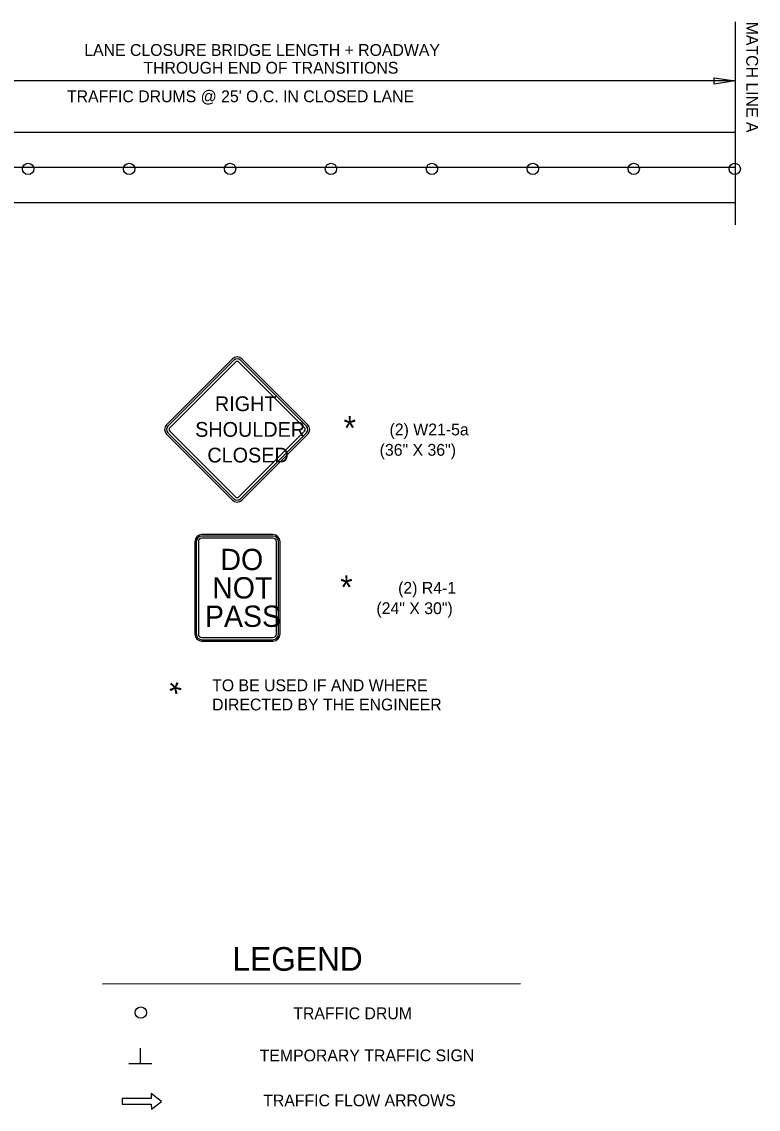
# Model space of a CAD drawing. Extents: x 1925873 to 1930787, y 596452 to 599617.
# Drawn here: x 1926416 to 1926790, y 596949 to 597501 of the extents above; entities that cross this region are included whole.
import ezdxf

# ---------------------------------------------------------------- set-up
doc = ezdxf.new("R2010")
doc.units = 0
for name, color, linetype in [('Default', 7, 'Continuous'), ('P_TC_Signs_Permanent', 7, 'Continuous'), ('P_TC_Signs_Temporary', 7, 'Continuous'), ('R_Border', 7, 'Continuous'), ('R_Border Prem', 7, 'Continuous'), ('R_MOT', 7, 'Continuous')]:
    doc.layers.add(name, color=color, linetype=linetype)

msp = doc.modelspace()

# ---------------------------------------------------------------- linework, layer by layer
at = {"layer": 'Default'}
for p, q in [((1926778.09, 597500.68), (1926778.09, 597397.67)), ((1926778.09, 597470.66), (1926333.71, 597470.66)), ((1926767.55, 597469.08), (1926767.55, 597472.24)), ((1926767.55, 597472.24), (1926778.09, 597470.66)), ((1926778.09, 597470.66), (1926767.55, 597469.08)), ((1925910.15, 597444.67), (1926778.09, 597444.67)), ((1925910.15, 597426.89), (1926778.09, 597426.89)), ((1925910.15, 597409.1), (1926778.09, 597409.1))]:
    msp.add_line(p, q, dxfattribs=at)
for centre in [(1926419.73, 597426.05), (1926470.9, 597426.05), (1926522.06, 597426.05), (1926573.22, 597426.05), (1926624.39, 597426.05), (1926675.55, 597426.05), (1926726.71, 597426.05), (1926777.88, 597426.05), (1926476.84, 596998.21)]:
    msp.add_circle(centre, 2.88, dxfattribs=at)
at = {"layer": 'P_TC_Signs_Permanent'}
for p, q in [((1926504.19, 597237.01), (1926504.19, 597190.21)), ((1926504.91, 597237.01), (1926504.91, 597190.21)), ((1926505.99, 597237.01), (1926505.99, 597190.21)), ((1926543.79, 597240.61), (1926507.79, 597240.61)), ((1926543.79, 597239.89), (1926507.79, 597239.89)), ((1926543.79, 597238.81), (1926507.79, 597238.81)), ((1926545.59, 597190.21), (1926545.59, 597237.01)), ((1926546.67, 597190.21), (1926546.67, 597237.01)), ((1926547.39, 597190.21), (1926547.39, 597237.01)), ((1926507.79, 597188.41), (1926543.79, 597188.41)), ((1926507.79, 597187.33), (1926543.79, 597187.33)), ((1926507.79, 597186.61), (1926543.79, 597186.61))]:
    msp.add_line(p, q, dxfattribs=at)
for centre, radius, start, end in [((1926507.79, 597237.01), 3.6, 90, 180), ((1926507.79, 597237.01), 2.88, 90, 180), ((1926507.79, 597237.01), 1.8, 90, 180), ((1926543.79, 597237.01), 3.6, 360, 90), ((1926543.79, 597237.01), 2.88, 360, 90), ((1926543.79, 597237.01), 1.8, 360, 90), ((1926507.79, 597190.21), 3.6, 180, 270), ((1926507.79, 597190.21), 2.88, 180, 270), ((1926507.79, 597190.21), 1.8, 180, 270), ((1926543.79, 597190.21), 3.6, 270, 360), ((1926543.79, 597190.21), 2.88, 270, 360), ((1926543.79, 597190.21), 1.8, 270, 360)]:
    msp.add_arc(centre, radius, start, end, dxfattribs=at)
at = {"layer": 'P_TC_Signs_Temporary'}
for p, q in [((1926489.87, 597296.31), (1926523.28, 597329.72)), ((1926490.53, 597295.64), (1926523.94, 597329.06)), ((1926491.46, 597294.72), (1926524.87, 597328.13)), ((1926526.46, 597328.13), (1926559.87, 597294.72)), ((1926527.39, 597329.06), (1926560.8, 597295.64)), ((1926528.05, 597329.72), (1926561.46, 597296.31)), ((1926523.28, 597258.12), (1926489.87, 597291.53)), ((1926523.94, 597258.79), (1926490.53, 597292.2)), ((1926524.87, 597259.71), (1926491.46, 597293.13)), ((1926559.87, 597293.13), (1926526.46, 597259.71)), ((1926560.8, 597292.2), (1926527.39, 597258.79)), ((1926561.46, 597291.53), (1926528.05, 597258.12))]:
    msp.add_line(p, q, dxfattribs=at)
for centre, radius, start, end in [((1926525.66, 597327.33), 3.38, 45, 135), ((1926525.66, 597327.33), 2.44, 45, 135), ((1926525.66, 597327.33), 1.13, 45, 135), ((1926492.25, 597293.92), 3.37, 135, 225), ((1926492.25, 597293.92), 2.44, 135, 225), ((1926492.25, 597293.92), 1.12, 135, 225), ((1926559.07, 597293.92), 1.12, 315, 45), ((1926559.07, 597293.92), 2.44, 315, 45), ((1926559.07, 597293.92), 3.37, 315, 45), ((1926525.66, 597260.51), 2.44, 225, 315), ((1926525.66, 597260.51), 1.13, 225, 315), ((1926525.66, 597260.51), 3.38, 225, 315)]:
    msp.add_arc(centre, radius, start, end, dxfattribs=at)
at = {"layer": 'R_Border'}
for p, q in [((1926457.41, 597012.85), (1926669.31, 597012.99)), ((1926476.59, 596972.34), (1926476.58, 596980.2)), ((1926482.32, 596972.17), (1926470.8, 596972.16))]:
    msp.add_line(p, q, dxfattribs=at)
at = {"layer": 'R_MOT'}
msp.add_lwpolyline([(1926482.15, 596949.21), (1926487.34, 596953.21), (1926482.14, 596957.21), (1926482.14, 596954.71), (1926467.43, 596954.7), (1926467.43, 596951.7), (1926482.14, 596951.71)], close=True, dxfattribs=at)

# ---------------------------------------------------------------- texts
at = {"layer": 'Default'}
for s, height, rotation, p in [('MATCH LINE A', 6, 270, (1926783.72, 597500.68)), ('LANE CLOSURE BRIDGE LENGTH + ROADWAY ', 5.9996, 360, (1926448.14, 597483.35)), ('THROUGH END OF TRANSITIONS', 5.9996, 360, (1926478.13, 597474.35)), ("TRAFFIC DRUMS @ 25' O.C. IN CLOSED LANE", 5.9996, 360, (1926439.4, 597459.87))]:
    msp.add_text(s, height=height, rotation=rotation, dxfattribs=at).set_placement(p)
at = {"layer": 'P_TC_Signs_Permanent'}
for s, rotation, p in [('DO', 360, (1926517.18, 597222.61)), ('NOT', 359.9596, (1926513, 597208.22)), ('PASS', 360, (1926509.34, 597193.81))]:
    msp.add_text(s, height=10.8, rotation=rotation, dxfattribs=at).set_placement(p)
at = {"layer": 'P_TC_Signs_Temporary'}
for s, p in [('RIGHT', (1926514.39, 597303.22)), ('SHOULDER', (1926504.37, 597290.2)), ('CLOSED', (1926510.55, 597277.18))]:
    msp.add_text(s, height=7.5, rotation=360, dxfattribs=at).set_placement(p)
at = {"layer": 'R_Border'}
for s, height, rotation, p in [('(2) W21-5a', 6, 360, (1926602.9, 597290.92)), ('(36" X 36")', 6, 360, (1926597.89, 597280.6)), ('(2) R4-1', 6, 360, (1926607.25, 597210.61)), ('(24" X 30")', 6, 360, (1926596.25, 597200.29)), ('*', 12, 45, (1926498.27, 597154.47)), ('TO BE USED IF AND WHERE', 6, 360, (1926512.98, 597161.2)), ('DIRECTED BY THE ENGINEER', 6, 360, (1926512.98, 597151.45)), ('LEGEND', 12, 0.0388, (1926523.31, 597019.42)), ('TRAFFIC DRUM', 6, 0.0388, (1926554.11, 596994.83)), ('TEMPORARY TRAFFIC SIGN', 6, 0.0388, (1926537.08, 596973.47)), ('TRAFFIC FLOW ARROWS', 6, 0.0388, (1926538.86, 596950.67))]:
    msp.add_text(s, height=height, rotation=rotation, dxfattribs=at).set_placement(p)
at = {"layer": 'R_Border Prem'}
for p in [(1926579.61, 597288.68), (1926577.92, 597207.93)]:
    msp.add_text('*', height=12, rotation=360, dxfattribs=at).set_placement(p)

doc.saveas('drawing.dxf')
